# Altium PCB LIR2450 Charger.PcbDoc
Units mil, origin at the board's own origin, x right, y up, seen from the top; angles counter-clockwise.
Board outline 1479.99 x 1200 mil, 2 copper layers (Top Layer, Bottom Layer), stack 64.8 mil thick; 8 components, 6 nets, 26 pads, 20 vias.
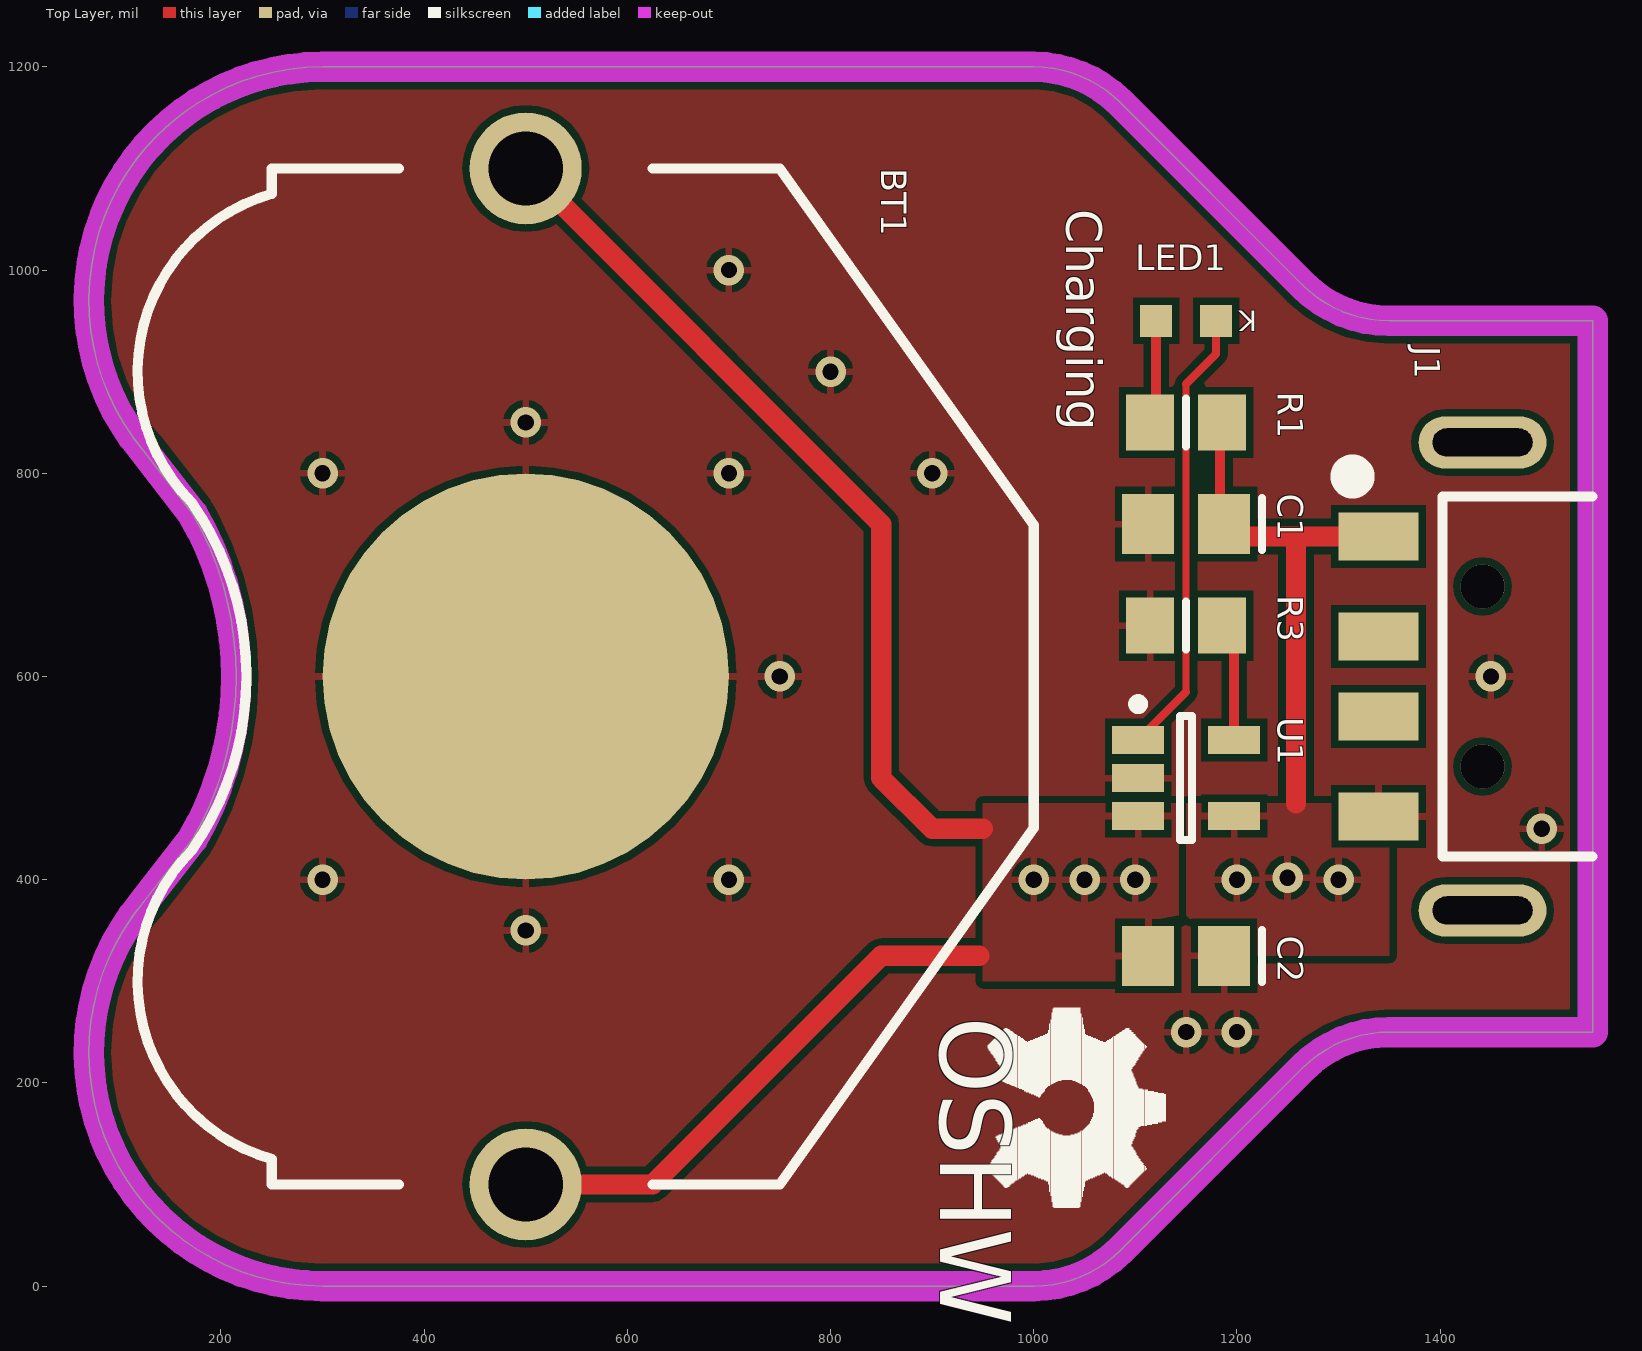
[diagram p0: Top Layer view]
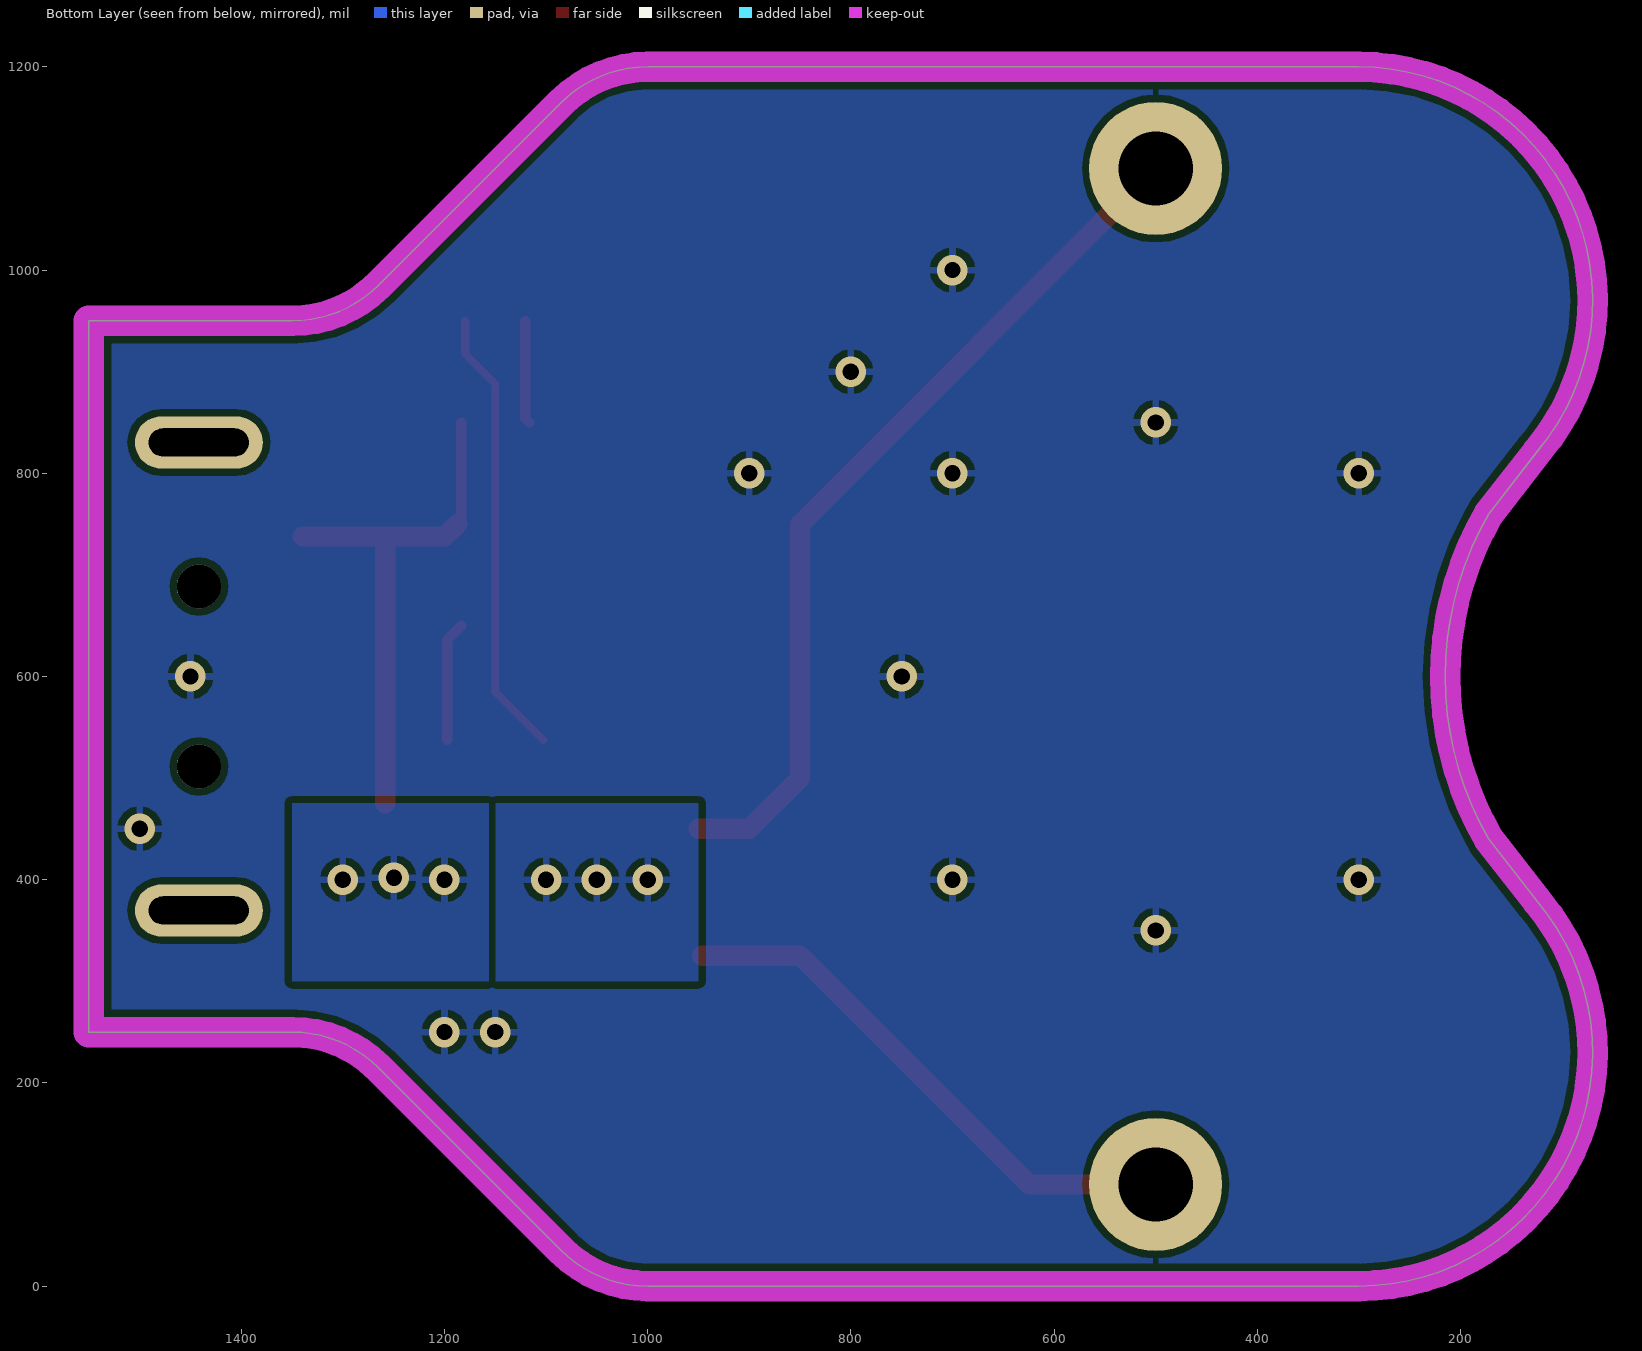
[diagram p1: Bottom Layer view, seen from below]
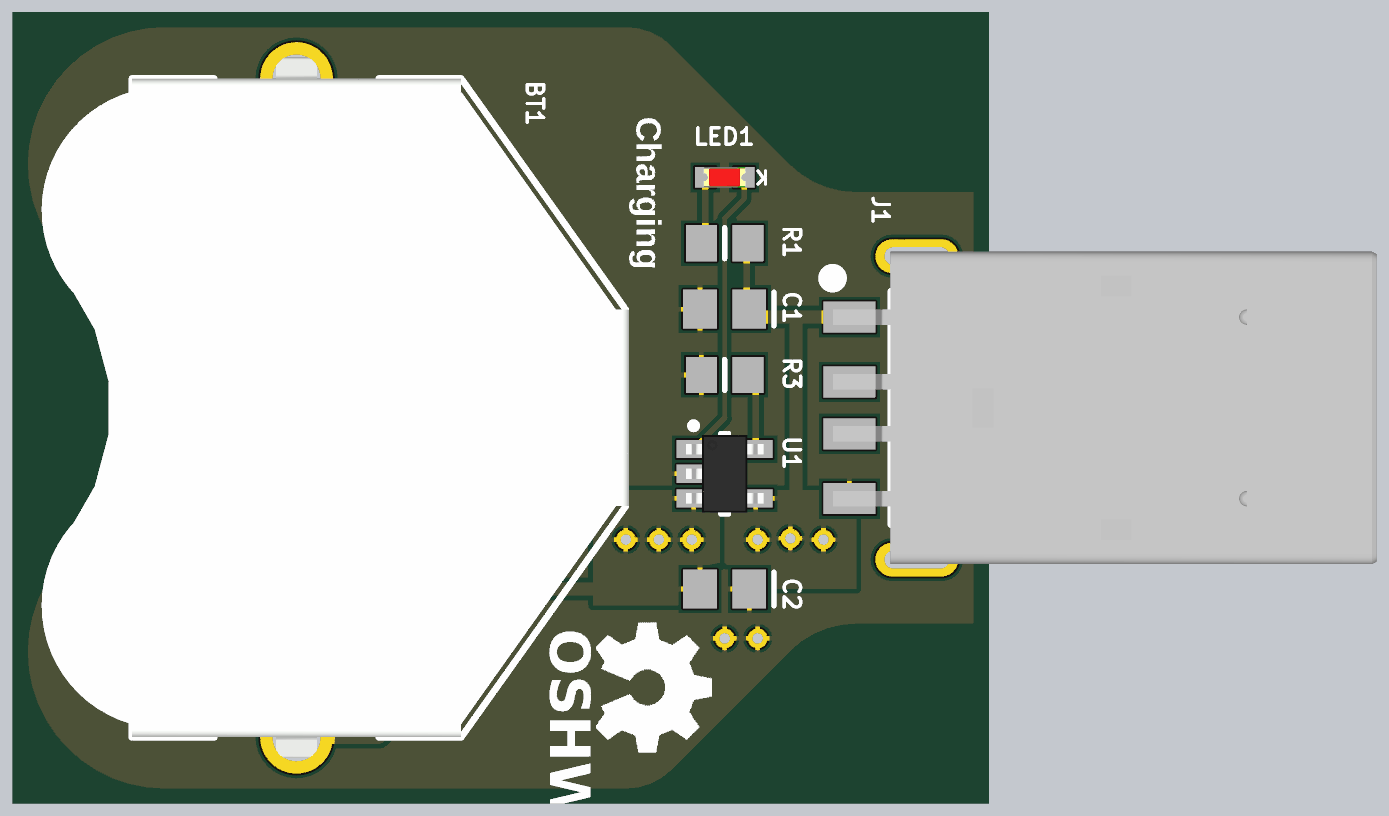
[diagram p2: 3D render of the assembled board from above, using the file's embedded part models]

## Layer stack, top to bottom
Top Layer: signal copper 1.4
Dielectric: core 62, FR-4, Dk 4.8
Bottom Layer: signal copper 1.4

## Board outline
123.81,377.84 172.13,440 ccw(c-105,600) 172.13,760 123.81,822.16 cw(c300,970) 300,1200 1000,1200 cw(c1000,1079.29) 1085.36,1164.64 1264.64,985.36 ccw(c1350,1070.71) 1350,950 1550,950 1550,250 1350,250 ccw(c1350,129.29) 1264.64,214.64 1085.36,35.36 cw(c1000,120.71) 1000,0 300,0 cw(c300,230)

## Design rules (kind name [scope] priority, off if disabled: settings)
Clearance [All vs OnLayer('Board Outline')] p1: gap=30
Clearance "Clearance~Gold Phoenix" [All] p2: gap=7 // Gold Phoenix minimum clearance rule
HoleSize "HoleSize~Gold Phoenix PCB" [All] p1: absolutevalues=TRUE maxlimit=251 minlimit=16 maxpercent=80.000 minpercent=20.000 // Gold Phoenix Hole Size Rule For Single Sided & Double Sided Designs.
MinimumAnnularRing "MinimumAnnularRing~Gold Phoenix PCB" [All] p1: minimumring=7 // Gold Phoenix Minimum Annular Ring (Double Sided)
MinimumSolderMaskSliver "MinimumSolderMaskSliver~Gold Phoenix" [All] p1: minsoldermaskwidth=3
PlaneClearance "Plane Clearance~Gold Phoenix PCB" [All] p1: clearance=15 // Gold Phoenix Power Plane Clearance Rule (Double Sided)
PlaneConnect "Plane Connect~Gold Phoenix PCB" [All] p1: planeconnectstyle=Relief reliefexpansion=10 reliefentries=4 reliefconductorwidth=7 reliefairgap=15 // Gold Phoenix Power Plane Connect Rule (Double Sided)
PolygonConnect "Polygon Connect~Gold Phoenix" [All] p1: connectstyle=Relief reliefconductorwidth=7 reliefentries=4 polygonreliefangle="90 Angle" // Gold Phoenix Polygon Connect Style (Double Sided)
RoutingVias "Routing Vias~Gold Phoenix PCB" [All] p1: holewidth=16 width=30 viastyle="Through Hole" minholewidth=15 minwidth=30 maxholewidth=20 maxwidth=40 // Sunstone Circuits Routing Vias Rule (Double Sided)
SMDToCorner [All] p1: distance=50000
ShortCircuit "ShortCircuit~Gold Phoenix" [All] p1: allowed=FALSE // Gold Phoenix PCB Short Circuit Rule~Do Not Allow (Double Sided)
SilkscreenOverComponentPads [All] p1: minsilkscreentomaskgap=10
SolderMaskExpansion "SolderMaskExpansion~Sunstone Circuits" [All] p1: expansion=3 // Sunstone Circuits Solder Mask Expansion Rule (Double Sided)
UnRoutedNet "Unrouted non-GND nets" [Not InNet('GND')] p1:
UnRoutedNet "Unrouted GND net" [InNet('GND') or InNet('SGND') or InNet('EARTH')] p2:
ViasUnderSMD "ViasUnderSMD~Sunstone Circuits" [All] p1: allowed=FALSE // Sunstone Circuits Vias Under SMD~Do Not Allow (Double Sided)
Width "Width~Gold Phoenix PCB" [All] p1: maxlimit=100 minlimit=7 preferedwidth=10 // Gold Phoenix Minimum Width Rule (Double Sided)
21 further rules are at their usual default settings.

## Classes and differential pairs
net class Undefined: GND VBAT VUSB

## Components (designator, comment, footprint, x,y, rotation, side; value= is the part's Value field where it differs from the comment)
BT1 "3009" 3009 500,600 r90 top
C1 "C0805" 0805 1150,750 r180 top
C2 "C0805" 0805 1150,325 r180 top
J1 "48037-2200" 480372200 1550,600 r0 top
LED1 "LS Q976-NR-1" LED-SMD-0603-RED 1150,950 r0 top
R1 "470" RESC2012N 1150,850 r0 top
R3 "20K" RESC2012N 1150,650 r0 top
U1 "MCP73832T-2ACI/OT" SOT-23-OT5_M 1150,500 r0 top

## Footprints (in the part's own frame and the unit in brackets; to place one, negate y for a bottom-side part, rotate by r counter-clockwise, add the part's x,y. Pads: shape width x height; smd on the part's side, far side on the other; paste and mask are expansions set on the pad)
0805 [mm] "Chip Capacitor; Body 2.0 x 1.2 mm (LxW typ)"
  rect 1.3x1.5 smd: 1(-0.95,0) 2(0.95,0)
  silkscreen extent -1.9,-0.65 -1.9,0.65
3009 [mm] "Battery Holder, CR2450, Keystone Part Number 3009"
  round 2.8 / inner round 3.327 / far side round 3.327 hole 1.854: 1(-12.7,0) 1(12.7,0)
  round 10.16 smd: 2(0,0)
  silkscreen extent -12.7,-12.7 12.7,9.7, body extent -13.51,-12.83 13.51,9.78, height 5.84
480372200 [mm] "USB, A, Male, Molex 48037-2200"
  rect 2x1.2 smd: 1(-5.35,3.5) 2(-5.35,1) 3(-5.35,-1) 4(-5.35,-3.5)
  oval 3.2x1.3 hole 0.7 slot 2.5 at 0 deg: 5(-2.75,5.85) 6(-2.75,-5.85)
  round 1.1 hole 1.1: MH1(-2.75,2.25) MH2(-2.75,-2.25)
  silkscreen extent -6.1,-4.5 0,5.1, body extent -5.98,-6.02 14.97,6.03, height 2.1
LED-SMD-0603-RED [mm] "LED, SMD, 0603, Red"
  rect 0.8x0.8 smd: 1(-0.75,0) 2(0.75,0)
  body extent -0.81,-0.4 0.81,0.4, height 0.6
RESC2012N [mm] "Chip Resistor, Body 2.0x1.3mm, IPC Medium Density"
  rect 1.2x1.4 smd: 1(-0.9,0) 2(0.9,0)
  silkscreen extent 0,-0.6 0,0.6, body extent -1,-0.6 1,0.6, height 0.65
SOT-23-OT5_M [mm] "SOT23, 5-Leads, Body 2.9x1.6mm, Pitch 0.95mm, Lead Span 2.7mm, IPC Low Density"
  rect 1.3x0.7 smd: 1(-1.2,0.95) 2(-1.2,0) 3(-1.2,-0.95) 4(1.2,-0.95) 5(1.2,0.95)
  silkscreen extent -1.32,-1.55 0.15,1.97, body extent -1.5,-1.5 1.5,1.5, height 1.45

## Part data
BT1: "Battery Holder, CR2450, Keystone model 3009"
C1 C2: "Ceramic Chip Capacitor - Standard"
J1: "USB 1.1, Right Angle, SMT, A Type, Receptacle, 4 Position, White"
LED1: "LED CHIPLED 633NM RED 0603 SMD"
R1: library part ERJ-6GEYJ471V, "RES 470 OHM 1/8W 5% 0805 SMD"
R3: library part ERJ-6GEYJ203V, "RES 20K OHM 1/8W 5% 0805 SMD"
U1: "IC LI-ION/LI-POLY CTRLR SOT23-5"

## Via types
v1: diameter 30, hole 16, Top Layer to Bottom Layer, 20 vias

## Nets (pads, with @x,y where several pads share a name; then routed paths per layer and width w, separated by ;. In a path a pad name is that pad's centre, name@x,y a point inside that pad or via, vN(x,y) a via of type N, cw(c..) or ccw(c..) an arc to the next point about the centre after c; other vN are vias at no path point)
GND: BT1.2 C1.2 C2.1 J1.4 R3.1 U1.2
  other v1: 1150,250 1200,250 500,350 300,400 700,400 1500,450 750,600 1450,600 300,800 700,800 900,800 500,850 800,900 700,1000
NetLED1_1: LED1.1 R1.1 | length 101.6
  Top Layer w10: R1.1@1116.54,850 1120.47,853.94 LED1.1
NetLED1_2: LED1.2 U1.1 | length 444.4
  Top Layer w7: 1150,584.65 1150,887.75
  Top Layer w8: U1.1 1150,584.65 ; 1150,887.75 1179.53,917.28 LED1.2
PROG: R3.2 U1.5 | length 118.3
  Top Layer w10: R3.2@1183.46,650 1197.24,636.22 U1.5
VBAT: BT1.1 C2.2 U1.3 | length 1405.4
  Top Layer w20: BT1.1@500,100 625,100 850,325 946.5,325 ; BT1.1@500,1100 850,750 850,500 900,450 950,450
  other v1: 1000,400 1050,400 1100,400
VUSB: C1.1 J1.1 R1.2 U1.4 | length 521.5
  Top Layer w10: R1.2@1183.46,850 1183.46,753.94 C1.1
  Top Layer w20: C1.1 1199.61,737.8 1258.19,737.8 ; 1258.19,475 1258.19,737.8 ; J1.1 1258.19,737.8
  other v1: 1200,400 1300,400 1249.78,401.81
pads on no net: J1.2 J1.3 J1.5 J1.6 J1.MH1 J1.MH2

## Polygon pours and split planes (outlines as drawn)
GND on Top Layer "Top GND" (solid, pour order 14): 123.81,377.84 172.13,440 ccw(c-105,600) 172.13,760 123.81,822.16 cw(c300,970) 300,1200 1000,1200 cw(c1000,1079.29) 1085.36,1164.64 1264.64,985.36 ccw(c1350,1070.71) 1350,950 1550,950 1550,250 1350,250 ccw(c1350,129.29) 1264.64,214.64 1085.36,35.36 cw(c1000,120.71) 1000,0 300,0 cw(c300,230)
VUSB on Top Layer "Top VUSB" (solid, pour order 12): 1150,475 1150,325 1350,325 1350,475
VBAT on Top Layer "Top VBAT" (solid, pour order 13): 950,475 1150,475 1150,300 950,300
GND on Bottom Layer "Bottom GND" (solid, pour order 18): 123.81,377.84 172.13,440 ccw(c-105,600) 172.13,760 123.81,822.16 cw(c300,970) 300,1200 1000,1200 cw(c1000,1079.29) 1085.36,1164.64 1264.64,985.36 ccw(c1350,1070.71) 1350,950 1550,950 1550,250 1350,250 ccw(c1350,129.29) 1264.64,214.64 1085.36,35.36 cw(c1000,120.71) 1000,0 300,0 cw(c300,230)
VBAT on Bottom Layer "B VBAT" (solid, pour order 11): 950,475 1150,475 1150,300 950,300
VUSB on Bottom Layer "B VUSB" (solid, pour order 10): 1156.49,475 1350,475 1350,300 1156.49,300

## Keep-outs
Keep-Out Layer:
  the board outline again, w30

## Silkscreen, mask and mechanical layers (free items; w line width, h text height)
Top Overlay:
  drawing of 321 lines, arcs and shapes, not listed
  text "Charging" at 1020,1060 h60 r270
  text "OSHW" at 885,265 h120 r270
Board Outline:
  the board outline again, w0

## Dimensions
69,970 to 1552,1200 on Mechanical 1
0,1200 to 0,0 on Mechanical 1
